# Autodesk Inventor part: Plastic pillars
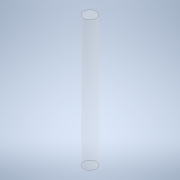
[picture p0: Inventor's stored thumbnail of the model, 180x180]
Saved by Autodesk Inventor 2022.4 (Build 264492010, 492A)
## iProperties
Created: 2023-10
Part Number: Plastic pillars
Material: PMMA Plastic
Document SubType Name: Modeling
Designer: tmass
Density: 1.188 g/cm^3
Appearance: Polycarbonate - Clear
Author: tmass
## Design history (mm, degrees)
sketch "Sketch1"
  geometry: C1 r 2.4 at (0, 0); 1 further point
  constraints: 1 centre point, 1 coincident
  dimensions: "d0" = 4.8 diameter of C1
extrude "Extrusion1" new body sketch "Sketch1" distance "d1" = 50; taper "d2" = 0 deg
body "Solid1"
